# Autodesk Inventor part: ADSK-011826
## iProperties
Shininess: 0.0
Length Units: 11272
Angle Units: 11279
Time Units: 11290
Mass Units: 11286
Length Display Precision: 3
Angle Display Precision: 2
Compacted: True
Created: 1999-08
Part Number: ADSK-011826
Document SubType Name: Modeling
Density: 0.0
Volumn: 0.0
Area: 0.0
PropertySet Name: Model Information
Control State: 0
Master: False
Checked Out: False
Revision Number: -
Title: ADSK-011826
